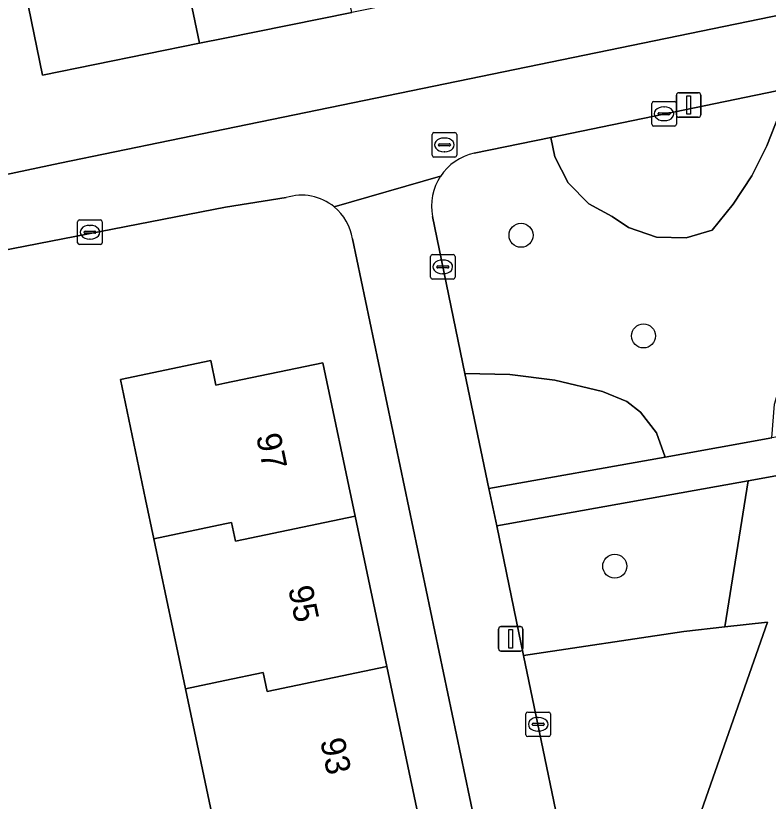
# Model space of a CAD drawing. Extents: x 162989 to 165008, y 383432 to 384338.
# Drawn here: x 163991.48 to 164022.13, y 384061.55 to 384093.56 of the extents above; entities that cross this region are included whole.
import ezdxf

# ---------------------------------------------------------------- set-up
doc = ezdxf.new("R2010")
doc.units = 0
for name, color, linetype in [('IMGEO_Boom', 7, 'Continuous'), ('IMGEO_Erf', 7, 'Continuous'), ('IMGEO_Groenvoorziening', 7, 'Continuous'), ('IMGEO_Kolk', 7, 'Continuous'), ('IMGEO_Lichtmast', 7, 'Continuous'), ('IMGEO_Pand', 7, 'Continuous'), ('IMGEO_Pand_nummerreeks', 7, 'Continuous'), ('IMGEO_Rioolput', 7, 'Continuous'), ('IMGEO_Voetpad_open', 7, 'Continuous')]:
    doc.layers.add(name, color=color, linetype=linetype)

msp = doc.modelspace()

# ---------------------------------------------------------------- linework, layer by layer
at = {"layer": 'IMGEO_Boom'}
for centre in [(164012.06, 384084.611), (164017.048, 384080.51), (164015.877, 384071.127)]:
    msp.add_circle(centre, 0.489, dxfattribs=at)
at = {"layer": 'IMGEO_Erf'}
for points in [[(164031.509, 384097.056), (164030.077, 384103.527), (164029.066, 384103.318), (164030.008, 384098.74), (164023.797, 384097.479), (164017.642, 384096.23), (164011.359, 384094.954), (164005.165, 384093.696), (164000, 384092.648), (163998.962, 384092.437), (163992.575, 384091.141), (163991.669, 384095.597), (163991.511, 384096.377), (163992.423, 384096.563), (163991.787, 384099.691)], [(163988.61, 384094.965), (163989.701, 384089.167), (163990.131, 384086.885), (163993.273, 384087.551), (164000, 384088.938), (164030.286, 384095.184)], [(164002.492, 384086.15), (164000.024, 384085.754), (163984.737, 384082.778)], [(164014.374, 384040.675), (164005.195, 384084.465)]]:
    msp.add_lwpolyline(points, dxfattribs=at)
msp.add_lwpolyline([(164001.04, 384053.598), (164000, 384058.517), (163999.727, 384059.814), (163998.397, 384066.129), (163997.109, 384072.248), (163996.772, 384073.846), (163995.753, 384078.741), (163999.425, 384079.505), (163999.634, 384078.503), (164000, 384078.579), (164003.994, 384079.409), (164005.307, 384073.161), (164006.593, 384067.041), (164007.919, 384060.726), (164009.226, 384054.508), (164010.464, 384048.615), (164011.821, 384042.157), (164006.945, 384041.133), (164006.783, 384041.905), (164003.634, 384041.243), (164002.607, 384046.137), (164002.278, 384047.705)], close=True, dxfattribs=at)
for centre, radius, start, end in [((164003.121, 384084.147), 2.099, 50.5863, 107.4348), ((164003.118, 384084.147), 2.101, 8.7, 50.5149)]:
    msp.add_arc(centre, radius, start, end, dxfattribs=at)
at = {"layer": 'IMGEO_Groenvoorziening'}
for points in [[(164027.234, 384084.027), (164027.363, 384085.271), (164028.104, 384087.376), (164028.888, 384088.974), (164029.836, 384090.482), (164030.762, 384092.207), (164022.866, 384090.577), (164022.57, 384089.528), (164022.077, 384088.251), (164021.453, 384087.032), (164020.705, 384085.885), (164019.841, 384084.823), (164018.782, 384084.514), (164017.58, 384084.535), (164016.443, 384084.927), (164015.777, 384085.376), (164014.82, 384085.89), (164013.978, 384086.743), (164013.441, 384087.814), (164013.28, 384088.599), (164010.158, 384087.954)], [(164008.459, 384085.375), (164009.766, 384078.981), (164011.611, 384078.943), (164013.443, 384078.713), (164015.376, 384078.252), (164016.363, 384077.841), (164016.929, 384077.405), (164017.578, 384076.556), (164017.928, 384075.574), (164022.275, 384076.352), (164022.379, 384077.724), (164022.756, 384078.991), (164023.389, 384080.152), (164024.249, 384081.156), (164024.809, 384081.326), (164025.553, 384081.706), (164026.481, 384082.545), (164026.936, 384083.246), (164027.234, 384084.027)], [(164028.523, 384075.903), (164021.314, 384074.608), (164020.366, 384068.653), (164022.098, 384068.847), (164018.294, 384057.988), (164014.263, 384057.358), (164016.016, 384048.897)]]:
    msp.add_lwpolyline(points, dxfattribs=at)
for points in [[(164013.28, 384088.599), (164013.441, 384087.814), (164013.978, 384086.743), (164014.82, 384085.89), (164015.777, 384085.376), (164016.443, 384084.927), (164017.58, 384084.535), (164018.782, 384084.514), (164019.841, 384084.823), (164020.705, 384085.885), (164021.453, 384087.032), (164022.077, 384088.251), (164022.57, 384089.528), (164022.866, 384090.577)], [(164017.928, 384075.574), (164017.578, 384076.556), (164016.929, 384077.405), (164016.363, 384077.841), (164015.376, 384078.252), (164013.443, 384078.713), (164011.611, 384078.943), (164009.766, 384078.981), (164010.748, 384074.289)], [(164021.314, 384074.608), (164011.069, 384072.768), (164012.163, 384067.488), (164018.697, 384068.466), (164020.366, 384068.653)], [(164022.098, 384068.847), (164020.366, 384068.653), (164018.697, 384068.466), (164012.163, 384067.488), (164014.263, 384057.358), (164018.294, 384057.988)]]:
    msp.add_lwpolyline(points, close=True, dxfattribs=at)
for centre, radius, start, end in [((164010.602, 384085.814), 2.185, 101.7174, 146.6709), ((164010.606, 384085.811), 2.191, 146.6521, 191.468)]:
    msp.add_arc(centre, radius, start, end, dxfattribs=at)
at = {"layer": 'IMGEO_Kolk'}
for p, q in [((164017.385, 384089.137), (164017.385, 384089.989)), ((164017.46, 384090.063), (164018.312, 384090.063)), ((164017.873, 384089.843), (164017.898, 384089.843)), ((164018.386, 384089.989), (164018.386, 384089.137)), ((164017.644, 384089.557), (164017.644, 384089.569)), ((164018.082, 384089.52), (164017.684, 384089.52)), ((164017.687, 384089.606), (164018.085, 384089.606)), ((164018.128, 384089.569), (164018.128, 384089.557)), ((164017.896, 384089.283), (164017.871, 384089.283)), ((164018.312, 384089.063), (164017.46, 384089.063)), ((163994.004, 384084.311), (163994.004, 384085.163)), ((163994.079, 384085.237), (163994.931, 384085.237)), ((163994.492, 384085.017), (163994.517, 384085.017)), ((163995.005, 384085.163), (163995.005, 384084.311)), ((163994.263, 384084.731), (163994.263, 384084.743)), ((163994.701, 384084.694), (163994.303, 384084.694)), ((163994.306, 384084.78), (163994.704, 384084.78)), ((163994.747, 384084.743), (163994.747, 384084.731)), ((163994.515, 384084.457), (163994.49, 384084.457)), ((163994.931, 384084.237), (163994.079, 384084.237)), ((164008.374, 384082.899), (164008.374, 384083.751)), ((164008.449, 384083.825), (164009.301, 384083.825)), ((164009.375, 384083.751), (164009.375, 384082.899)), ((164008.676, 384083.368), (164009.074, 384083.368)), ((164008.862, 384083.605), (164008.887, 384083.605)), ((164008.633, 384083.319), (164008.633, 384083.331)), ((164009.071, 384083.282), (164008.673, 384083.282)), ((164008.885, 384083.045), (164008.86, 384083.045)), ((164009.117, 384083.331), (164009.117, 384083.319)), ((164009.301, 384082.825), (164008.449, 384082.825)), ((164012.334, 384065.184), (164013.186, 384065.184)), ((164012.259, 384064.258), (164012.259, 384065.11)), ((164012.747, 384064.964), (164012.772, 384064.964)), ((164013.26, 384065.11), (164013.26, 384064.258)), ((164012.518, 384064.678), (164012.518, 384064.69)), ((164012.956, 384064.641), (164012.558, 384064.641)), ((164012.561, 384064.727), (164012.959, 384064.727)), ((164013.002, 384064.69), (164013.002, 384064.678)), ((164013.186, 384064.184), (164012.334, 384064.184)), ((164012.77, 384064.404), (164012.745, 384064.404))]:
    msp.add_line(p, q, dxfattribs=at)
for points in [[(164017.385, 384089.137), (164017.385, 384089.989)], [(164017.46, 384090.063), (164018.312, 384090.063)], [(164018.386, 384089.989), (164018.386, 384089.137)], [(164018.312, 384089.063), (164017.46, 384089.063)], [(163994.004, 384084.311), (163994.004, 384085.163)], [(163994.079, 384085.237), (163994.931, 384085.237)], [(163995.005, 384085.163), (163995.005, 384084.311)], [(163994.931, 384084.237), (163994.079, 384084.237)], [(164008.374, 384082.899), (164008.374, 384083.751)], [(164008.449, 384083.825), (164009.301, 384083.825)], [(164009.375, 384083.751), (164009.375, 384082.899)], [(164009.301, 384082.825), (164008.449, 384082.825)], [(164012.334, 384065.184), (164013.186, 384065.184)], [(164012.259, 384064.258), (164012.259, 384065.11)], [(164013.26, 384065.11), (164013.26, 384064.258)], [(164013.186, 384064.184), (164012.334, 384064.184)]]:
    msp.add_lwpolyline(points, dxfattribs=at)
for centre, radius, start, end in [((164017.462, 384089.987), 0.0765, 91.552, 178.448), ((164017.462, 384089.987), 0.0765, 91.552, 178.448), ((164018.31, 384089.987), 0.0765, 1.552, 88.448), ((164018.31, 384089.987), 0.0765, 1.552, 88.448), ((164017.684, 384089.566), 0.0403, 85.8775, 175.7526), ((164017.681, 384089.556), 0.0366, 178.938, 274.7102), ((164018.085, 384089.563), 0.043, 264.8664, 352.4533), ((164018.089, 384089.568), 0.0386, 1.7309, 96.639), ((164017.462, 384089.139), 0.0765, 181.552, 268.448), ((164017.462, 384089.139), 0.0765, 181.552, 268.448), ((164018.31, 384089.139), 0.0765, 271.552, 358.448), ((164018.31, 384089.139), 0.0765, 271.552, 358.448), ((163994.081, 384085.161), 0.0765, 91.552, 178.448), ((163994.081, 384085.161), 0.0765, 91.552, 178.448), ((163994.929, 384085.161), 0.0765, 1.552, 88.448), ((163994.929, 384085.161), 0.0765, 1.552, 88.448), ((163994.303, 384084.74), 0.0403, 85.8775, 175.7526), ((163994.3, 384084.73), 0.0366, 178.938, 274.7102), ((163994.704, 384084.737), 0.043, 264.8664, 352.4533), ((163994.708, 384084.742), 0.0386, 1.7309, 96.639), ((163994.081, 384084.313), 0.0765, 181.552, 268.448), ((163994.081, 384084.313), 0.0765, 181.552, 268.448), ((163994.929, 384084.313), 0.0765, 271.552, 358.448), ((163994.929, 384084.313), 0.0765, 271.552, 358.448), ((164008.451, 384083.749), 0.0765, 91.552, 178.448), ((164008.451, 384083.749), 0.0765, 91.552, 178.448), ((164009.299, 384083.749), 0.0765, 1.552, 88.448), ((164009.299, 384083.749), 0.0765, 1.552, 88.448), ((164008.673, 384083.328), 0.0403, 85.8775, 175.7526), ((164009.078, 384083.33), 0.0386, 1.7309, 96.639), ((164008.67, 384083.318), 0.0366, 178.938, 274.7102), ((164009.074, 384083.325), 0.043, 264.8664, 352.4533), ((164008.451, 384082.901), 0.0765, 181.552, 268.448), ((164008.451, 384082.901), 0.0765, 181.552, 268.448), ((164009.299, 384082.901), 0.0765, 271.552, 358.448), ((164009.299, 384082.901), 0.0765, 271.552, 358.448), ((164012.336, 384065.108), 0.0765, 91.552, 178.448), ((164012.336, 384065.108), 0.0765, 91.552, 178.448), ((164013.184, 384065.108), 0.0765, 1.552, 88.448), ((164013.184, 384065.108), 0.0765, 1.552, 88.448), ((164012.558, 384064.687), 0.0403, 85.8775, 175.7526), ((164012.555, 384064.677), 0.0366, 178.938, 274.7102), ((164012.959, 384064.684), 0.043, 264.8664, 352.4533), ((164012.963, 384064.689), 0.0386, 1.7309, 96.639), ((164012.336, 384064.26), 0.0765, 181.552, 268.448), ((164012.336, 384064.26), 0.0765, 181.552, 268.448), ((164013.184, 384064.26), 0.0765, 271.552, 358.448), ((164013.184, 384064.26), 0.0765, 271.552, 358.448)]:
    msp.add_arc(centre, radius, start, end, dxfattribs=at)
for centre, major_axis, ratio, start_param, end_param in [((164017.872, 384089.563), (-0.387, 0.002), 0.722429, 4.712389, 7.853982), ((164017.897, 384089.563), (-0.39, 0.002), 0.717154, 1.570796, 4.712389), ((163994.491, 384084.737), (-0.387, 0.002), 0.722429, 4.712389, 7.853982), ((163994.516, 384084.737), (-0.39, 0.002), 0.717154, 1.570796, 4.712389), ((164008.861, 384083.325), (-0.387, 0.002), 0.722429, 4.712389, 7.853982), ((164008.886, 384083.325), (-0.39, 0.002), 0.717154, 1.570796, 4.712389), ((164012.746, 384064.684), (-0.387, 0.002), 0.722429, 4.712389, 7.853982), ((164012.771, 384064.684), (-0.39, 0.002), 0.717154, 1.570796, 4.712389)]:
    msp.add_ellipse(centre, major_axis=major_axis, ratio=ratio, start_param=start_param, end_param=end_param, dxfattribs=at)
at = {"layer": 'IMGEO_Lichtmast'}
for p, q in [((164018.489, 384090.42), (164019.279, 384090.42)), ((164019.279, 384090.42), (164018.489, 384090.42)), ((164018.389, 384089.52), (164018.389, 384090.32)), ((164018.389, 384090.32), (164018.389, 384089.52)), ((164019.379, 384090.32), (164019.379, 384089.52)), ((164019.379, 384089.52), (164019.379, 384090.32)), ((164019.279, 384089.42), (164018.489, 384089.42)), ((164018.489, 384089.42), (164019.279, 384089.42)), ((164011.243, 384068.666), (164012.033, 384068.666)), ((164012.033, 384068.666), (164011.243, 384068.666)), ((164011.143, 384067.766), (164011.143, 384068.566)), ((164011.143, 384068.566), (164011.143, 384067.766)), ((164012.133, 384068.566), (164012.133, 384067.766)), ((164012.133, 384067.766), (164012.133, 384068.566)), ((164012.033, 384067.666), (164011.243, 384067.666)), ((164011.243, 384067.666), (164012.033, 384067.666))]:
    msp.add_line(p, q, dxfattribs=at)
for points in [[(164018.809, 384090.295), (164018.959, 384090.295), (164018.959, 384089.545), (164018.809, 384089.545), (164018.809, 384090.295)], [(164011.563, 384068.541), (164011.713, 384068.541), (164011.713, 384067.791), (164011.563, 384067.791), (164011.563, 384068.541)]]:
    msp.add_lwpolyline(points, dxfattribs=at)
for centre, start, end in [((164018.489, 384090.32), 90, 180), ((164018.489, 384090.32), 90, 180), ((164019.279, 384090.32), 0, 90), ((164019.279, 384090.32), 360, 90), ((164018.489, 384089.52), 180, 270), ((164018.489, 384089.52), 180, 270), ((164019.279, 384089.52), 270, 0), ((164019.279, 384089.52), 270, 0), ((164011.243, 384068.566), 90, 180), ((164011.243, 384068.566), 90, 180), ((164012.033, 384068.566), 0, 90), ((164012.033, 384068.566), 360, 90), ((164011.243, 384067.766), 180, 270), ((164011.243, 384067.766), 180, 270), ((164012.033, 384067.766), 270, 0), ((164012.033, 384067.766), 270, 0)]:
    msp.add_arc(centre, 0.1, start, end, dxfattribs=at)
at = {"layer": 'IMGEO_Pand'}
for points in [[(163998.25, 384101.018), (163999.018, 384097.265), (163998.008, 384097.06), (163998.962, 384092.437), (164000, 384092.648), (164005.165, 384093.696), (164004.211, 384098.318), (164005.221, 384098.523), (164004.456, 384102.263), (164000, 384101.37)], [(163998.25, 384101.018), (163996.684, 384100.703), (163991.787, 384099.691), (163992.423, 384096.563), (163991.511, 384096.377), (163991.669, 384095.597), (163992.575, 384091.141), (163998.962, 384092.437), (163998.008, 384097.06), (163999.018, 384097.265)], [(164005.307, 384073.161), (164003.994, 384079.409), (164000, 384078.579), (163999.634, 384078.503), (163999.425, 384079.505), (163995.753, 384078.741), (163996.772, 384073.846), (163997.109, 384072.248), (164000, 384072.854), (164000.273, 384072.911), (164000.433, 384072.141)], [(164005.307, 384073.161), (164000.433, 384072.141), (164000.273, 384072.911), (164000, 384072.854), (163997.109, 384072.248), (163998.397, 384066.129), (164000, 384066.465), (164001.558, 384066.791), (164001.718, 384066.021), (164006.593, 384067.041)], [(163999.727, 384059.814), (164000, 384059.872), (164002.884, 384060.476), (164003.044, 384059.706), (164007.919, 384060.726), (164006.593, 384067.041), (164001.718, 384066.021), (164001.558, 384066.791), (164000, 384066.465), (163998.397, 384066.129)]]:
    msp.add_lwpolyline(points, close=True, dxfattribs=at)
at = {"layer": 'IMGEO_Rioolput'}
for p, q in [((164008.44, 384087.871), (164008.44, 384088.723)), ((164008.515, 384088.797), (164009.367, 384088.797)), ((164008.928, 384088.577), (164008.953, 384088.577)), ((164009.441, 384088.723), (164009.441, 384087.871)), ((164008.699, 384088.291), (164008.699, 384088.303)), ((164009.137, 384088.254), (164008.739, 384088.254)), ((164008.742, 384088.34), (164009.14, 384088.34)), ((164009.183, 384088.303), (164009.183, 384088.291)), ((164008.951, 384088.017), (164008.926, 384088.017)), ((164009.367, 384087.797), (164008.515, 384087.797))]:
    msp.add_line(p, q, dxfattribs=at)
for points in [[(164008.44, 384087.871), (164008.44, 384088.723)], [(164008.515, 384088.797), (164009.367, 384088.797)], [(164009.441, 384088.723), (164009.441, 384087.871)], [(164009.367, 384087.797), (164008.515, 384087.797)]]:
    msp.add_lwpolyline(points, dxfattribs=at)
for centre, radius, start, end in [((164008.517, 384088.721), 0.0765, 91.552, 178.448), ((164008.517, 384088.721), 0.0765, 91.552, 178.448), ((164009.365, 384088.721), 0.0765, 1.552, 88.448), ((164009.365, 384088.721), 0.0765, 1.552, 88.448), ((164008.739, 384088.3), 0.0403, 85.8775, 175.7526), ((164008.736, 384088.29), 0.0366, 178.938, 274.7102), ((164009.14, 384088.297), 0.043, 264.8664, 352.4533), ((164009.144, 384088.302), 0.0386, 1.7309, 96.639), ((164008.517, 384087.873), 0.0765, 181.552, 268.448), ((164008.517, 384087.873), 0.0765, 181.552, 268.448), ((164009.365, 384087.873), 0.0765, 271.552, 358.448), ((164009.365, 384087.873), 0.0765, 271.552, 358.448)]:
    msp.add_arc(centre, radius, start, end, dxfattribs=at)
for centre, major_axis, ratio, start_param, end_param in [((164008.927, 384088.297), (-0.387, 0.002), 0.722429, 4.712389, 7.853982), ((164008.952, 384088.297), (-0.39, 0.002), 0.717154, 1.570796, 4.712389)]:
    msp.add_ellipse(centre, major_axis=major_axis, ratio=ratio, start_param=start_param, end_param=end_param, dxfattribs=at)
at = {"layer": 'IMGEO_Voetpad_open'}
for points in [[(164030.286, 384095.184), (164000, 384088.938), (163993.273, 384087.551), (163990.131, 384086.885), (163989.701, 384089.167), (163988.027, 384088.819), (163985.008, 384088.192), (163983.154, 384087.807), (163983.612, 384085.606), (163979.868, 384084.828), (163980.518, 384081.956), (163984.737, 384082.778), (164000.024, 384085.754), (164002.492, 384086.15)], [(164010.158, 384087.954), (164013.28, 384088.599), (164022.866, 384090.577)], [(164004.454, 384085.769), (164008.776, 384087.015)], [(164008.776, 384087.015), (164004.454, 384085.769)], [(164012.163, 384067.488), (164011.069, 384072.768), (164010.748, 384074.289), (164009.766, 384078.981), (164008.459, 384085.375)], [(164005.195, 384084.465), (164014.374, 384040.675), (164017.619, 384047.508)], [(164016.016, 384048.897), (164014.263, 384057.358), (164012.163, 384067.488)]]:
    msp.add_lwpolyline(points, dxfattribs=at)
msp.add_lwpolyline([(164028.523, 384075.903), (164028.805, 384077.525), (164022.275, 384076.352), (164017.928, 384075.574), (164010.748, 384074.289), (164011.069, 384072.768), (164021.314, 384074.608)], close=True, dxfattribs=at)
for centre, radius, start, end in [((164010.602, 384085.814), 2.185, 101.7174, 146.6709), ((164010.606, 384085.811), 2.191, 146.6521, 191.468), ((164003.121, 384084.147), 2.099, 50.5863, 107.4348), ((164003.118, 384084.147), 2.101, 8.7, 50.5149)]:
    msp.add_arc(centre, radius, start, end, dxfattribs=at)

# ---------------------------------------------------------------- texts
at = {"layer": 'IMGEO_Pand_nummerreeks'}
for s, p in [('97', (164001.266, 384076.439)), ('95', (164002.571, 384070.231)), ('93', (164003.875, 384064.022))]:
    msp.add_text(s, height=1, rotation=281.8658, dxfattribs=at).set_placement(p)

doc.saveas('drawing.dxf')
